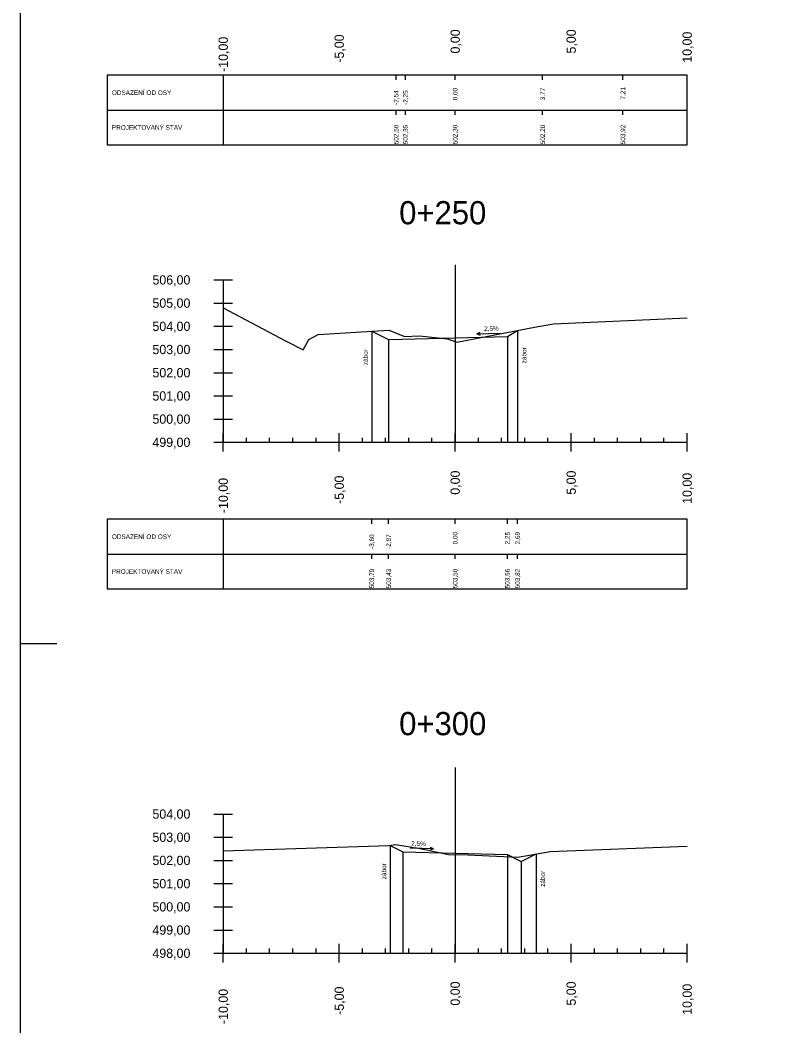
# Model space of a CAD drawing. Extents: x -631407 to -631215, y -1089700 to -1088598.
# Drawn here: x -631407.01 to -631374.65, y -1088900.51 to -1088857.16 of the extents above; entities that cross this region are included whole.
import ezdxf

# ---------------------------------------------------------------- set-up
doc = ezdxf.new("R2010")
doc.units = 0
for name, color, linetype in [('08_LEGENDA_HV', 7, 'Continuous'), ('59', 7, 'Continuous'), ('DTM-Breaklines', 7, 'Continuous'), ('NIVELETA_VYSKY', 7, 'Continuous'), ('REZ_BODY', 7, 'Continuous'), ('REZ_ODSTUPY', 7, 'Continuous'), ('REZ_POPIS', 7, 'Continuous'), ('REZ_RAMY', 7, 'Continuous'), ('REZ_STANICENI', 7, 'Continuous'), ('REZ_SVISLE', 7, 'Continuous'), ('REZ_TENKA', 7, 'Continuous'), ('REZ_TLUSTA', 7, 'Continuous'), ('TABULKA_POPIS', 7, 'Continuous'), ('TEREN', 7, 'Continuous'), ('zábor', 7, 'Continuous')]:
    doc.layers.add(name, color=color, linetype=linetype)

msp = doc.modelspace()

# ---------------------------------------------------------------- linework, layer by layer
at = {"layer": '08_LEGENDA_HV'}
msp.add_lwpolyline([(-631215.384, -1088943.435), (-631215.384, -1088765.235), (-631407.014, -1088765.235), (-631407.014, -1088943.435)], close=True, dxfattribs=at)
at = {"layer": '59'}
for p, q in [((-631398.658, -1088868.359), (-631397.858, -1088868.359)), ((-631398.258, -1088868.359), (-631398.258, -1088875.359)), ((-631398.658, -1088869.359), (-631397.858, -1088869.359)), ((-631398.658, -1088870.359), (-631397.858, -1088870.359)), ((-631398.658, -1088871.359), (-631397.858, -1088871.359)), ((-631398.658, -1088872.359), (-631397.858, -1088872.359)), ((-631398.658, -1088873.359), (-631397.858, -1088873.359)), ((-631398.658, -1088874.359), (-631397.858, -1088874.359)), ((-631398.658, -1088875.359), (-631397.858, -1088875.359)), ((-631398.658, -1088891.381), (-631397.858, -1088891.381)), ((-631398.258, -1088891.381), (-631398.258, -1088897.381)), ((-631398.658, -1088892.381), (-631397.858, -1088892.381)), ((-631398.658, -1088893.381), (-631397.858, -1088893.381)), ((-631398.658, -1088894.381), (-631397.858, -1088894.381)), ((-631398.658, -1088895.381), (-631397.858, -1088895.381)), ((-631398.658, -1088896.381), (-631397.858, -1088896.381)), ((-631398.658, -1088897.381), (-631397.858, -1088897.381))]:
    msp.add_line(p, q, dxfattribs=at)
at = {"layer": 'DTM-Breaklines'}
msp.add_line((-631407.014, -1088884.035), (-631405.434, -1088884.035), dxfattribs=at)
at = {"layer": 'REZ_RAMY'}
for p, q in [((-631403.258, -1088859.539), (-631403.258, -1088862.539)), ((-631398.258, -1088859.539), (-631398.258, -1088862.539)), ((-631390.802, -1088859.739), (-631390.802, -1088859.539)), ((-631390.402, -1088859.739), (-631390.402, -1088859.539)), ((-631388.258, -1088859.739), (-631388.258, -1088859.539)), ((-631384.488, -1088859.739), (-631384.488, -1088859.539)), ((-631381.027, -1088859.739), (-631381.027, -1088859.539)), ((-631403.258, -1088861.039), (-631378.258, -1088861.039)), ((-631390.802, -1088861.239), (-631390.802, -1088861.039)), ((-631390.402, -1088861.239), (-631390.402, -1088861.039)), ((-631388.258, -1088861.239), (-631388.258, -1088861.039)), ((-631384.488, -1088861.239), (-631384.488, -1088861.039)), ((-631381.027, -1088861.239), (-631381.027, -1088861.039)), ((-631398.258, -1088878.678), (-631398.258, -1088881.678)), ((-631391.854, -1088878.878), (-631391.854, -1088878.678)), ((-631391.129, -1088878.878), (-631391.129, -1088878.678)), ((-631388.258, -1088878.878), (-631388.258, -1088878.678)), ((-631386.008, -1088878.878), (-631386.008, -1088878.678)), ((-631385.571, -1088878.878), (-631385.571, -1088878.678)), ((-631403.258, -1088880.178), (-631378.258, -1088880.178)), ((-631391.854, -1088880.378), (-631391.854, -1088880.178)), ((-631391.129, -1088880.378), (-631391.129, -1088880.178)), ((-631388.258, -1088880.378), (-631388.258, -1088880.178)), ((-631386.008, -1088880.378), (-631386.008, -1088880.178)), ((-631385.571, -1088880.378), (-631385.571, -1088880.178))]:
    msp.add_line(p, q, dxfattribs=at)
for points in [[(-631403.258, -1088859.539), (-631403.258, -1088862.539), (-631378.258, -1088862.539), (-631378.258, -1088859.539)], [(-631403.258, -1088878.678), (-631403.258, -1088881.678), (-631378.258, -1088881.678), (-631378.258, -1088878.678)]]:
    msp.add_lwpolyline(points, close=True, dxfattribs=at)
at = {"layer": 'REZ_SVISLE'}
for points in [[(-631391.854, -1088870.57), (-631391.854, -1088874.359), (-631391.854, -1088874.859), (-631391.854, -1088875.359)], [(-631385.571, -1088870.542), (-631385.571, -1088874.359), (-631385.571, -1088874.859), (-631385.571, -1088875.359)], [(-631391.129, -1088870.932), (-631391.129, -1088874.359), (-631391.129, -1088874.859), (-631391.129, -1088875.359)], [(-631388.258, -1088870.86), (-631388.258, -1088874.359), (-631388.258, -1088874.859), (-631388.258, -1088875.359)], [(-631386.008, -1088870.804), (-631386.008, -1088874.359), (-631386.008, -1088874.859), (-631386.008, -1088875.359)], [(-631391.062, -1088892.73), (-631391.062, -1088896.381), (-631391.062, -1088896.881), (-631391.062, -1088897.381)], [(-631390.508, -1088893.008), (-631390.508, -1088896.381), (-631390.508, -1088896.881), (-631390.508, -1088897.381)], [(-631388.258, -1088893.064), (-631388.258, -1088896.381), (-631388.258, -1088896.881), (-631388.258, -1088897.381)], [(-631386.008, -1088893.12), (-631386.008, -1088896.381), (-631386.008, -1088896.881), (-631386.008, -1088897.381)], [(-631384.771, -1088893.101), (-631384.771, -1088896.381), (-631384.771, -1088896.881), (-631384.771, -1088897.381)], [(-631385.408, -1088893.42), (-631385.408, -1088896.381), (-631385.408, -1088896.881), (-631385.408, -1088897.381)]]:
    msp.add_lwpolyline(points, dxfattribs=at)
at = {"layer": 'REZ_TENKA'}
for p, q in [((-631397.258, -1088875.359), (-631397.258, -1088875.159)), ((-631396.258, -1088875.359), (-631396.258, -1088875.159)), ((-631395.258, -1088875.359), (-631395.258, -1088875.159)), ((-631394.258, -1088875.359), (-631394.258, -1088875.159)), ((-631392.258, -1088875.359), (-631392.258, -1088875.159)), ((-631391.258, -1088875.359), (-631391.258, -1088875.159)), ((-631390.258, -1088875.359), (-631390.258, -1088875.159)), ((-631389.258, -1088875.359), (-631389.258, -1088875.159)), ((-631387.258, -1088875.359), (-631387.258, -1088875.159)), ((-631386.258, -1088875.359), (-631386.258, -1088875.159)), ((-631385.258, -1088875.359), (-631385.258, -1088875.159)), ((-631384.258, -1088875.359), (-631384.258, -1088875.159)), ((-631382.258, -1088875.359), (-631382.258, -1088875.159)), ((-631381.258, -1088875.359), (-631381.258, -1088875.159)), ((-631380.258, -1088875.359), (-631380.258, -1088875.159)), ((-631379.258, -1088875.359), (-631379.258, -1088875.159)), ((-631397.258, -1088897.381), (-631397.258, -1088897.181)), ((-631396.258, -1088897.381), (-631396.258, -1088897.181)), ((-631395.258, -1088897.381), (-631395.258, -1088897.181)), ((-631394.258, -1088897.381), (-631394.258, -1088897.181)), ((-631392.258, -1088897.381), (-631392.258, -1088897.181)), ((-631391.258, -1088897.381), (-631391.258, -1088897.181)), ((-631390.258, -1088897.381), (-631390.258, -1088897.181)), ((-631389.258, -1088897.381), (-631389.258, -1088897.181)), ((-631387.258, -1088897.381), (-631387.258, -1088897.181)), ((-631386.258, -1088897.381), (-631386.258, -1088897.181)), ((-631385.258, -1088897.381), (-631385.258, -1088897.181)), ((-631384.258, -1088897.381), (-631384.258, -1088897.181)), ((-631382.258, -1088897.381), (-631382.258, -1088897.181)), ((-631381.258, -1088897.381), (-631381.258, -1088897.181)), ((-631380.258, -1088897.381), (-631380.258, -1088897.181)), ((-631379.258, -1088897.381), (-631379.258, -1088897.181))]:
    msp.add_line(p, q, dxfattribs=at)
at = {"layer": 'REZ_TLUSTA'}
for p, q in [((-631388.258, -1088867.711), (-631388.258, -1088875.359)), ((-631398.258, -1088875.759), (-631398.258, -1088874.959)), ((-631398.258, -1088875.359), (-631378.258, -1088875.359)), ((-631393.258, -1088875.759), (-631393.258, -1088874.959)), ((-631388.258, -1088875.759), (-631388.258, -1088874.959)), ((-631383.258, -1088875.759), (-631383.258, -1088874.959)), ((-631378.258, -1088875.759), (-631378.258, -1088874.959)), ((-631388.258, -1088889.381), (-631388.258, -1088897.381)), ((-631398.258, -1088897.781), (-631398.258, -1088896.981)), ((-631393.258, -1088897.781), (-631393.258, -1088896.981)), ((-631388.258, -1088897.781), (-631388.258, -1088896.981)), ((-631383.258, -1088897.781), (-631383.258, -1088896.981)), ((-631378.258, -1088897.781), (-631378.258, -1088896.981)), ((-631398.258, -1088897.381), (-631378.258, -1088897.381))]:
    msp.add_line(p, q, dxfattribs=at)
at = {"layer": 'TEREN'}
for points in [[(-631398.258, -1088869.569), (-631395.566, -1088870.987), (-631394.814, -1088871.376), (-631394.574, -1088870.923), (-631394.162, -1088870.71), (-631391.12, -1088870.525), (-631390.938, -1088870.597), (-631390.441, -1088870.804), (-631389.795, -1088870.769), (-631388.584, -1088870.906), (-631388.185, -1088871.049), (-631384.834, -1088870.399), (-631384.02, -1088870.255), (-631378.258, -1088869.996)], [(-631391.854, -1088870.57), (-631391.129, -1088870.932), (-631388.258, -1088870.86), (-631386.008, -1088870.804), (-631385.571, -1088870.542)], [(-631398.258, -1088892.971), (-631391.11, -1088892.737), (-631390.838, -1088892.698), (-631389.841, -1088892.851), (-631388.553, -1088893.122), (-631387.704, -1088893.14), (-631385.575, -1088893.246), (-631385.136, -1088893.169), (-631384.16, -1088892.989), (-631378.258, -1088892.766)], [(-631391.062, -1088892.73), (-631390.508, -1088893.008), (-631388.258, -1088893.064), (-631386.008, -1088893.12), (-631385.408, -1088893.42), (-631384.771, -1088893.101)]]:
    msp.add_lwpolyline(points, dxfattribs=at)
at = {"layer": 'zábor'}
for p, q in [((-631387.325, -1088870.681), (-631387.188, -1088870.616)), ((-631387.325, -1088870.681), (-631386.317, -1088870.656)), ((-631387.325, -1088870.681), (-631387.185, -1088870.739)), ((-631389.191, -1088892.884), (-631390.199, -1088892.859)), ((-631389.191, -1088892.884), (-631389.331, -1088892.942)), ((-631389.191, -1088892.884), (-631389.327, -1088892.82))]:
    msp.add_line(p, q, dxfattribs=at)

# ---------------------------------------------------------------- texts
at = {"layer": 'NIVELETA_VYSKY'}
for s, p in [('502,50', (-631390.702, -1088862.515)), ('502,35', (-631390.302, -1088862.515)), ('502,30', (-631388.158, -1088862.515)), ('502,20', (-631384.388, -1088862.515)), ('503,92', (-631380.927, -1088862.515)), ('503,79', (-631391.754, -1088881.654)), ('503,43', (-631391.029, -1088881.654)), ('503,50', (-631388.158, -1088881.654)), ('503,56', (-631385.908, -1088881.654)), ('503,82', (-631385.471, -1088881.654))]:
    msp.add_text(s, height=0.2, rotation=90, dxfattribs=at).set_placement(p)
at = {"layer": 'REZ_BODY'}
for s, p in [('0,00', (-631388.158, -1088860.618)), ('3,77', (-631384.388, -1088860.618)), ('7,21', (-631380.927, -1088860.585)), ('-2,54', (-631390.702, -1088860.816)), ('-2,25', (-631390.302, -1088860.816)), ('0,00', (-631388.158, -1088879.757)), ('2,25', (-631385.908, -1088879.757)), ('2,69', (-631385.471, -1088879.757)), ('-3,60', (-631391.754, -1088879.955)), ('-2,87', (-631391.029, -1088879.955))]:
    msp.add_text(s, height=0.2, rotation=90, dxfattribs=at).set_placement(p)
at = {"layer": 'REZ_ODSTUPY'}
for s, p in [('0,00', (-631388.058, -1088858.601)), ('5,00', (-631383.058, -1088858.601)), ('-10,00', (-631398.058, -1088859.395)), ('-5,00', (-631393.058, -1088858.998)), ('10,00', (-631378.058, -1088858.998)), ('0,00', (-631388.058, -1088877.618)), ('5,00', (-631383.058, -1088877.618)), ('-10,00', (-631398.058, -1088878.411)), ('-5,00', (-631393.058, -1088878.014)), ('10,00', (-631378.058, -1088878.014)), ('0,00', (-631388.058, -1088899.639)), ('5,00', (-631383.058, -1088899.639)), ('10,00', (-631378.058, -1088900.036)), ('-10,00', (-631398.058, -1088900.433)), ('-5,00', (-631393.058, -1088900.036))]:
    msp.add_text(s, height=0.4, rotation=90, dxfattribs=at).set_placement(p)
at = {"layer": 'REZ_POPIS'}
for s, p in [('506,00', (-631401.31, -1088868.559)), ('505,00', (-631401.31, -1088869.559)), ('504,00', (-631401.31, -1088870.559)), ('503,00', (-631401.31, -1088871.559)), ('502,00', (-631401.31, -1088872.559)), ('501,00', (-631401.31, -1088873.559)), ('500,00', (-631401.31, -1088874.559)), ('499,00', (-631401.31, -1088875.559)), ('504,00', (-631401.31, -1088891.581)), ('503,00', (-631401.31, -1088892.581)), ('502,00', (-631401.31, -1088893.581)), ('501,00', (-631401.31, -1088894.581)), ('500,00', (-631401.31, -1088895.581)), ('499,00', (-631401.31, -1088896.581)), ('498,00', (-631401.31, -1088897.581))]:
    msp.add_text(s, height=0.4, dxfattribs=at).set_placement(p)
at = {"layer": 'REZ_STANICENI'}
for s, p in [('0+250', (-631390.672, -1088865.963)), ('0+300', (-631390.672, -1088887.984))]:
    msp.add_text(s, height=1, dxfattribs=at).set_placement(p)
at = {"layer": 'TABULKA_POPIS'}
for s, p in [('ODSAZENÍ OD OSY', (-631403.058, -1088860.389)), ('PROJEKTOVANÝ STAV', (-631403.058, -1088861.889)), ('ODSAZENÍ OD OSY', (-631403.058, -1088879.528)), ('PROJEKTOVANÝ STAV', (-631403.058, -1088881.028))]:
    msp.add_text(s, height=0.2, dxfattribs=at).set_placement(p)
at = {"layer": 'zábor'}
for s, rotation, p in [('2,5%', 1.4321, (-631387.009, -1088870.56)), ('zábor', 90, (-631392.024, -1088872.033)), ('zábor', 90, (-631385.188, -1088871.956)), ('2,5%', 358.5679, (-631390.155, -1088892.747)), ('zábor', 90, (-631391.232, -1088894.194)), ('zábor', 90, (-631384.388, -1088894.516))]:
    msp.add_text(s, height=0.2, rotation=rotation, dxfattribs=at).set_placement(p)

doc.saveas('drawing.dxf')
